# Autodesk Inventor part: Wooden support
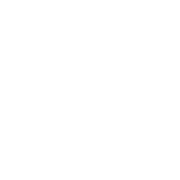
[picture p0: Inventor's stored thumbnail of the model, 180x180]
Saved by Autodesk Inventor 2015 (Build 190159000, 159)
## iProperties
Created: 2016-02
Part Number: Wooden support
Material: Wood (Birch)
Document SubType Name: Modeling
Designer: Hafliði
Density: 0.55 g/cm^3
Appearance: Birch - Natural Polished
Mass: 539 g
Surface Area: 658 cm^2
Volume: 980 cm^3
Author: Hafliði
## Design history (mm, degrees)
sketch "Sketch1"
  geometry: L1 (-35, 35)-(35, 35); L2 (35, 35)-(35, -35); L3 (35, -35)-(-35, -35); L4 (-35, -35)-(-35, 35); L5 (-35, 35)-(35, -35); L6 (35, 35)-(-35, -35); 1 further point
  constraints: 12 end point, 2 midpoint, 2 parallel, 1 horizontal, 1 perpendicular
  dimensions: "d0" = 70 distance of L2.end L3.end; "d1" = 70 distance of L1.end L2.end
extrude "Extrusion1" new body sketch "Sketch1" distance "d2" = 200; taper "d3" = 0 deg
body "Solid1"
